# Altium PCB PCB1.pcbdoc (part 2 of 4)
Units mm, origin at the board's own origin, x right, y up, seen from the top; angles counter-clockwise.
Board outline 94.87 x 122.3 mm, 4 copper layers (Top Layer, Inner1, Inner2, Bottom Layer); 129 components, 127 nets, 714 pads, 326 vias.
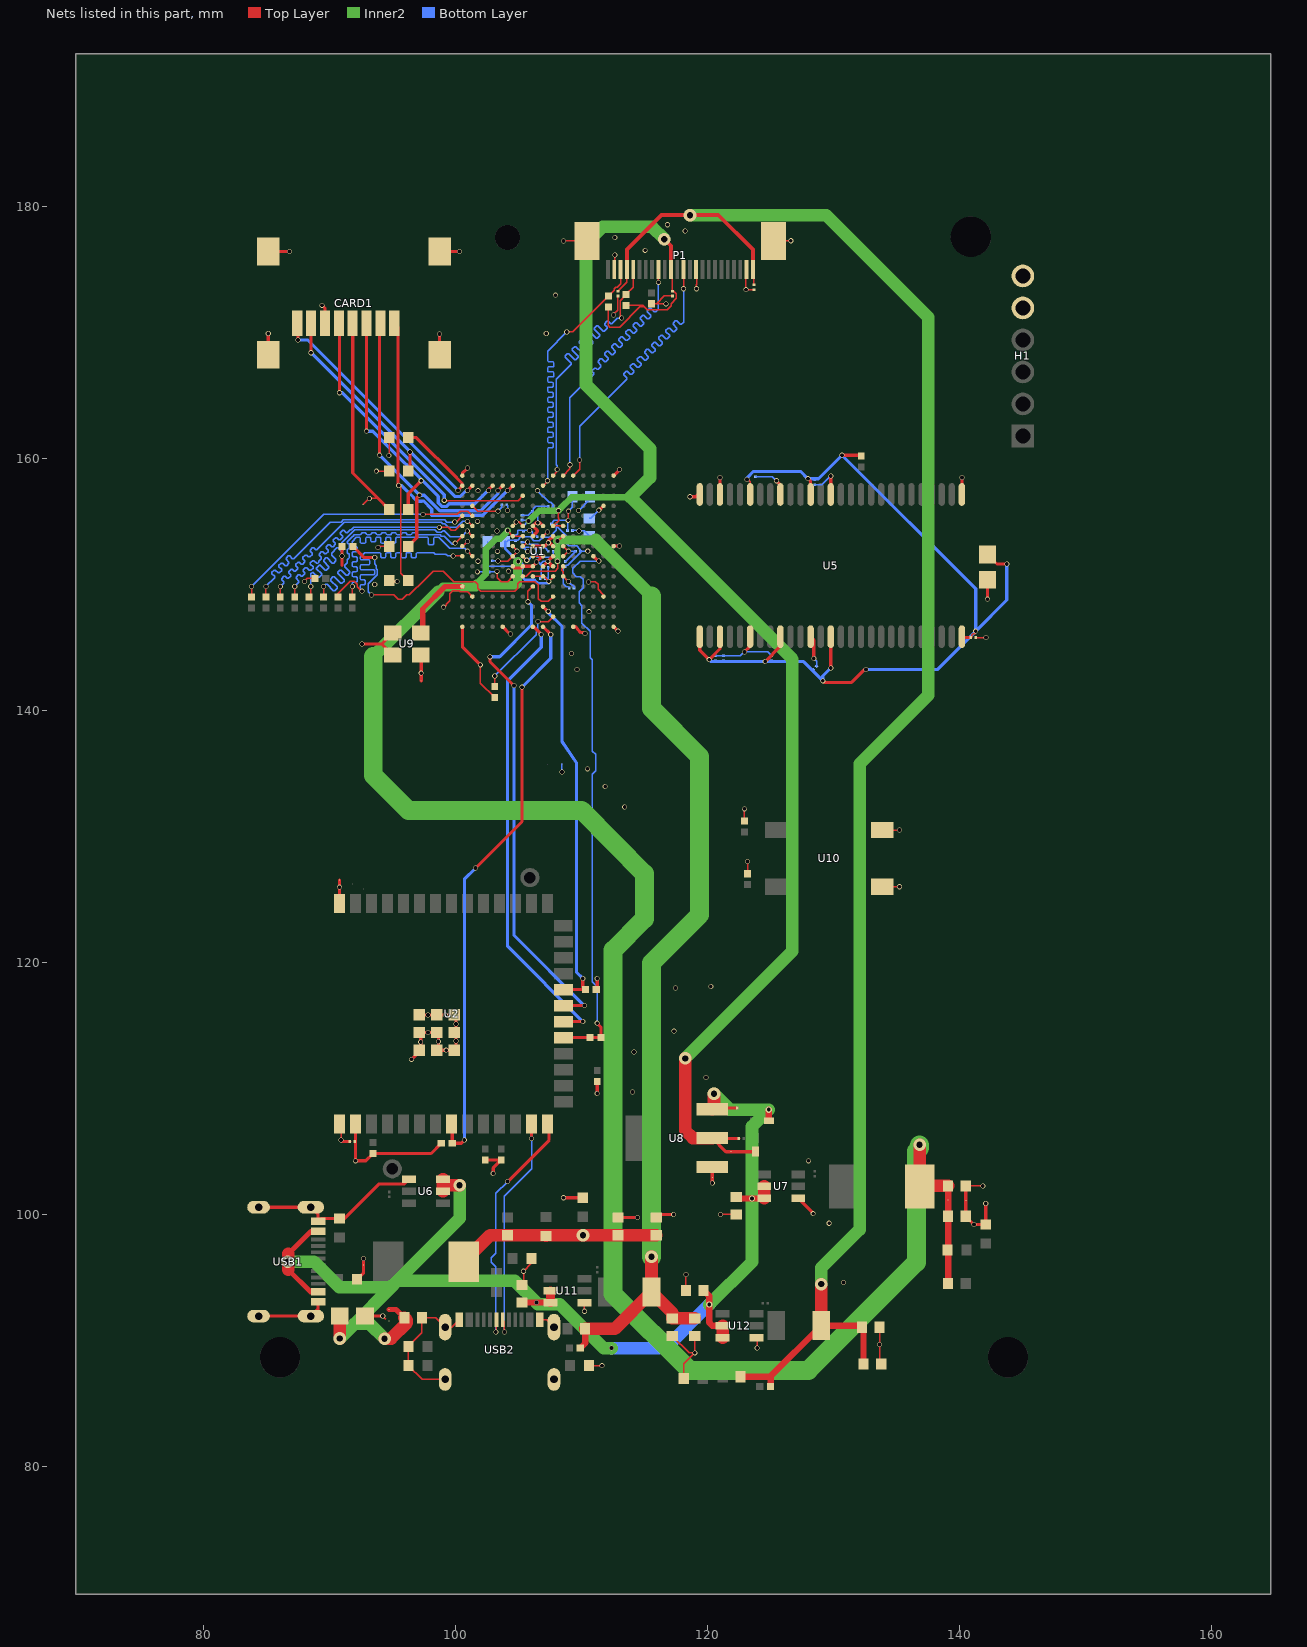
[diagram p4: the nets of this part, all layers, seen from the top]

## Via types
v1: diameter 0.4, hole 0.3, Top Layer to Bottom Layer, 311 vias
v2: diameter 1, hole 0.5, Top Layer to Bottom Layer, 12 vias
v3: diameter 0.5, hole 0.3, Top Layer to Bottom Layer, 3 vias

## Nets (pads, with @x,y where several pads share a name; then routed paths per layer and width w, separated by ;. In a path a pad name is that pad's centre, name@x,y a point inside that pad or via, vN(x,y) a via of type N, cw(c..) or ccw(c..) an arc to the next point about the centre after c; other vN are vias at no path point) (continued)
$2N5509: R24.2 U1.N10 | length 23.9
  Top Layer w0.1: v1(93.345,149.183) 95.104,149.183 95.464,148.823 95.798,148.823 96.158,149.183 96.351,149.183 97.595,150.427 97.595,150.432 98.231,151.068 99.024,151.068 99.856,150.236 101.567,150.236 101.771,150.032 101.771,149.696 101.995,149.472 103.911,149.472 103.918,149.479 104.388,149.479 104.395,149.472 104.711,149.472 104.935,149.696 104.935,150.054 105.117,150.236 106.311,150.236 106.571,149.976 106.571,148.896 106.795,148.672 107.371,148.672 U1.N10@107.753,149.054
  Top Layer w0.254: R24.2@91.873,153.035 92.762,152.146 v1(93.599,152.146)
  Bottom Layer w0.1: v1(93.345,149.183) 93.091,149.437 93.091,150.062 93.799,150.77 93.799,151.194 93.726,151.267 93.726,151.511 93.599,151.638 v1(93.599,152.146)
$2N5511: R25.2 U1.R10 | length 7.9
  Top Layer w0.1: R25.2@103.124,141.911 v1(103.124,142.748) ; v1(106.553,147.066) 107.365,147.066 U1.R10@107.753,147.454
  Bottom Layer w0.1: v1(103.124,142.748) 106.405,146.029 106.405,146.217 106.553,146.365 v1(106.553,147.066)
+1V1: C25.2 C27.2 C28.2 C41.1 C42.1 C43.1 C44.1 C49.1 C53.1 C54.1 C61.1 L2.2 pad.55@139.106,101.161 R15.2 U1.G6 U1.G7 U1.L8 U1.L9 U1.L10 | length 159.8
  Top Layer w0.1: v1@104.14,154.305 104.14,154.267 U1.G6@104.553,153.854 U1.G7@105.353,153.854 ; U1.L8@106.153,150.654 U1.L9@106.953,150.654 107.019,150.654 v1(107.412,150.262) 107.753,150.603 U1.L10@107.753,150.654
  Top Layer w0.5: C25.2@139.106,94.527 C28.2@139.106,99.861 pad.55@139.106,101.161 C27.2@139.106,102.274
  Top Layer w1: v2(136.842,105.537) L2.2@136.842,102.229 136.887,102.274 C27.2@139.106,102.274
  Inner2 w0.5: 101.639,149.81 101.651,149.821 101.651,150.075 102.404,150.829 102.404,152.808 103.247,153.651 103.553,153.651 104.148,154.246 v1(104.148,154.297)
  Inner2 w0.7: 98.629,149.429 99.01,149.81 101.639,149.81 ; 101.651,150.075 101.778,149.948 104.83,149.948 104.918,150.036 104.918,151.799 v1@104.962,151.844
  Inner2 w1: 93.482,144.282 98.629,149.429
  Inner2 w1.5: 93.482,144.282 93.482,134.864 96.266,132.08 110.016,132.08 112.608,129.488 112.608,129.454 114.998,127.064 114.998,123.464 112.522,120.988 112.522,93.695 118.587,87.63 128.016,87.63 136.588,96.202 136.588,105.029 136.842,105.283 v2(136.842,105.537)
  Bottom Layer w0.1: C61.1@104.078,153.416 104.182,153.52 104.93,153.52 105.203,153.792 105.923,153.792 106.23,153.485 106.674,153.485 106.963,153.776 107.482,153.776 108.018,154.313 108.018,154.559 ; C53.1@107.129,150.495 107.315,150.495 107.383,150.427 C49.1@107.383,151.384 ; C43.1@108.018,154.813 108.018,154.559 ; C44.1@109.034,153.543 109.034,153.654 108.129,154.559 108.018,154.559
  Bottom Layer w0.2: C61.1@103.951,153.416 103.951,152.883 v1(104.99,151.844) 105.118,151.844 105.212,151.75 105.212,151.746 105.318,151.64 105.318,151.224 C54.1@105.224,151.13 105.224,150.681 105.537,150.368 106.295,150.368 106.549,150.114 107.398,150.114 v1@107.412,150.127
+1V8: C29.1 C32.2 C35.1 C62.1 C63.1 P1.11 pad.55@121.87,104.992 R38.2 R39.2 U1.F10 U1.F11 U8.2 | length 124.4
  Top Layer w0.1: v1(108.185,155.869) 108.185,155.627 108.171,155.612 108.171,155.296 108.185,155.282 108.185,155.086 U1.F10@107.753,154.654 U1.F11@108.553,154.654 ; R38.2@112.141,172.033 112.141,171.57 112.137,171.566 112.137,170.565 112.268,170.434 113.05,170.434 114.649,172.033 114.985,172.033 ; R39.2@113.538,172.16 114.858,172.16 114.985,172.033 ; P1.11@117.11,175.02 117.209,174.922 117.209,173.823 117.221,173.811 C35.1@117.221,173.296 ; 117.332,173.296 117.533,173.095 117.533,172.717 117.115,172.299 117.115,172.121 116.797,171.802 115.216,171.802 114.985,172.033
  Top Layer w0.254: C29.1@122.487,106.045 120.419,106.045 121.472,104.992 pad.55@121.87,104.992 C32.2@123.825,104.992
  Top Layer w0.3: v2(116.586,177.419) 117.11,176.895 P1.11@117.11,175.02
  Top Layer w1: v2(118.237,112.395) 118.237,106.68 118.843,106.074 U8.2@120.39,106.074
  Inner2 w0.5: v1(105.801,155.054) 105.838,155.054 106.654,155.869 v1(108.185,155.869) 108.364,156.048 108.364,156.078 109.226,156.94 113.887,156.94
  Inner2 w1: v2(116.586,177.419) 115.607,178.398 111.686,178.398 110.363,177.075 110.363,165.862 115.443,160.782 115.443,158.496 113.887,156.94 126.746,144.082 126.746,120.904 v2(118.237,112.395)
  Bottom Layer w0.1: C63.1@105.283,155.126 105.729,155.126 v1(105.801,155.054) 105.41,154.663 C62.1@105.41,154.627
+2V5: C65.2 C67.2 C68.2 L3.2 R41.2 U1.G11 U1.L7 | length 86.3
  Top Layer w0.1: U1.L7@105.353,150.654 105.613,150.654 106.031,151.072 107.911,151.072 108.135,151.296 108.135,151.612 108.105,151.642 v1(108.105,151.854) ; v1(108.105,153.454) 108.505,153.854 U1.G11@108.553,153.854
  Top Layer w0.5: R41.2@109.907,89.408 110.301,89.802 C65.2@110.301,90.932
  Top Layer w1: C65.2@110.301,90.932 112.646,90.932 L3.2@115.567,93.853 ; v2(115.567,96.647) L3.2@115.567,93.853 ; C67.2@118.999,91.759 C68.2@117.221,91.759 117.221,92.199 L3.2@115.567,93.853
  Inner2 w0.5: v1(108.105,151.854) v1(108.105,153.454)
  Inner2 w0.7: v1(108.105,153.454) 108.194,153.543 111.125,153.543
  Inner2 w1: 111.125,153.543 115.567,149.101
  Inner2 w1.5: v2(115.567,96.647) 115.567,119.984 119.38,123.797 119.38,136.354 115.567,140.167 115.567,149.101
+2V8: C34.1 C70.2 C72.2 C73.2 C74.1 L4.2 P1.4 P1.24 R47.2 | length 139.5
  Top Layer w0.1: C34.1@112.903,173.296 113.611,174.004 P1.4@113.611,175.02 ; P1.24@123.612,175.017 123.698,174.931 C74.1@123.698,173.804
  Top Layer w0.3: P1.4@113.611,175.02 113.611,176.595 116.361,179.345 120.859,179.345 123.612,176.592 P1.24@123.612,175.017
  Top Layer w0.5: C70.2@122.62,87.122 124.965,87.122 ; R47.2@125.02,86.36 125.02,87.067 124.965,87.122 ; C73.2@132.269,91.059 132.142,91.186 L4.2@129.029,91.186 124.965,87.122 ; C72.2@132.396,88.138 C73.2@132.396,90.932
  Top Layer w1: L4.2@129.032,91.189 v2(129.032,94.488)
  Inner2 w1: v2(118.618,179.324) 129.413,179.324 137.541,171.196 137.541,141.224 132.08,135.763 132.08,98.806 129.032,95.758 v2(129.032,94.488)
+3V3: C8.1 C10.1 C11.1 C12.1 C13.1 C14.1 C15.2 C16.2 C17.2 C19.2 C22.2 C23.2 C37.1 C39.1 C40.1 C45.1 C46.1 C47.1 C48.1 C50.1 C51.1 C52.1 C55.1 C56.1 C57.1 C58.1 C59.1 CARD1.4 H1.5 L1.2 pad.55@92.679,156.358 R1.2 R3.1 R4.1 R5.2 R7.2 R11.2 R16.2 R17.2 R18.2 R19.2 R20.2 R21.2 R22.2 R23.1 U1.F6 U1.F7 U1.G9 U1.H6 U1.H7 U1.H11 U1.J6 U1.J7 U1.J11 U1.K11 U1.L6 U1.L11 U2.2 U5.1 U5.3 U5.9 U5.14 U5.27 U5.43 U5.49 U9.1 U9.4 | length 155.9
  Top Layer w0.1: v1(88.013,150.252) 88.256,150.495 R23.1@88.848,150.495 ; pad.55@92.679,156.358 v1(93.166,156.845) 93.858,156.845 93.86,156.847 ; v1(93.726,159.004) R18.2@94.751,159.004 ; v1(93.853,152.95) 93.938,153.035 R17.2@94.751,153.035 ; v1@94.751,160.274 R19.2@94.751,161.671 ; v1(103.305,151.054) 103.335,151.024 103.335,150.532 103.626,150.241 104.14,150.241 U1.L6@104.553,150.654 ; v1@103.378,151.892 103.575,151.892 103.595,151.872 104.171,151.872 U1.J6@104.553,152.254 104.881,152.582 v1(104.881,152.653) 104.881,152.726 U1.H6@104.553,153.054 ; U1.F6@104.553,154.654 104.821,154.922 v1(104.821,154.972) 105.035,154.972 U1.F7@105.353,154.654 ; U1.J7@105.353,152.254 105.664,151.943 v1@105.664,151.892 ; U1.H7@105.353,153.054 105.401,153.054 v1(105.737,153.39) ; U1.G9@106.953,153.854 107.277,154.178 v1(107.315,154.178) ; U1.K11@108.553,151.454 108.553,151.327 108.458,151.232 108.458,151.13 108.553,151.035 U1.L11@108.553,150.654 v1(108.966,150.241) ; U1.J11@108.553,152.254 108.953,152.654 v1(108.966,152.654) 108.566,153.054 U1.H11@108.553,153.054 ; v1(123.15,158.342) 123.217,158.342 123.394,158.165 U5.49@123.394,157.153 ; C14.1@140.902,145.796 140.985,145.879 140.985,145.99 141.103,146.108 141.214,146.108 141.292,146.186 v1(141.292,146.304)
  Top Layer w0.254: CARD1.4@91.848,170.739 91.848,158.859 93.86,156.847 R20.2@94.751,155.956 ; U2.2@92.197,107.201 92.075,107.079 v1(92.075,104.267) 92.889,104.267 R7.2@93.472,104.85 98.067,104.85 R5.2@98.881,105.664 ; v1(92.583,145.288) 94.164,145.288 ; R16.2@94.747,150.317 94.822,150.241 v1(95.377,150.241) ; U9.1@95.039,144.413 94.164,145.288 ; U9.4@95.039,146.163 94.164,145.288 ; R21.2@102.362,104.342 R22.2@103.632,104.342 102.997,103.707 v1(102.997,103.251) ; R3.1@111.177,117.856 111.252,117.931 v1(111.252,118.745) ; v1(111.252,109.601) R4.1@111.252,110.565 ; U5.1@119.394,145.996 119.394,144.787 v1(120.142,144.039) 120.994,144.891 U5.3@120.994,145.869 ; v1(124.587,143.891) 125.794,145.098 U5.9@125.794,145.869 ; v1(127.976,158.409) 128.194,158.191 U5.43@128.194,157.153 ; v1(129.159,142.367) 129.286,142.24 131.445,142.24 132.461,143.256 v1(132.588,143.256) ; v1(129.794,143.383) U5.14@129.794,145.869 ; v1(130.683,160.274) 132.132,160.274 R1.2@132.207,160.199 ; U5.27@140.194,145.869 140.267,145.796 C14.1@140.902,145.796 ; C8.1@142.24,152.384 142.986,151.638 v1(143.764,151.638)
  Top Layer w1: L1.2@100.663,96.266 102.757,98.36 C19.2@104.14,98.36 107.135,98.36 R11.2@107.188,98.307 107.241,98.36 v2(110.123,98.36) C23.2@112.903,98.36 C22.2@115.951,98.36
  Bottom Layer w0.1: C51.1@102.684,151.003 103.254,151.003 v1(103.305,151.054) ; C56.1@102.938,151.892 103.362,151.892 v1(103.37,151.884) ; C37.1@104.081,156.337 104.14,156.278 v1(104.14,155.889) ; C45.1@105.283,153.357 105.704,153.357 v1(105.737,153.39) 105.907,153.22 106.547,153.22 106.665,153.102 106.665,152.991 C46.1@106.748,152.908 107.12,152.908 C47.1@107.374,152.654 ; v1(105.664,151.933) 105.764,151.933 C57.1@106.104,152.273 ; C50.1@106.494,155.829 107.494,155.829 107.681,156.016 107.681,156.127 C39.1@107.764,156.21 107.764,156.321 107.563,156.522 107.437,156.522 v1(106.505,157.454) ; C52.1@108.712,151.833 C55.1@109.533,152.654 v1(108.966,152.654) ; v1(108.966,150.241) 109.162,150.045 109.214,150.045 109.415,149.844 C48.1@109.415,149.733 ; C40.1@109.288,154.305 109.75,154.305 v1(109.799,154.255) 110.221,154.255 C59.1@110.617,153.859 ; v1(109.777,155.877) 110.682,156.782 C58.1@110.682,156.972
  Bottom Layer w0.254: v1(120.142,144.039) 120.29,143.891 v1(124.587,143.891) 127.635,143.891 v1(129.159,142.367) 129.159,142.748 v1(129.794,143.383) ; v1(123.15,158.342) 123.15,158.49 123.638,158.977 127.408,158.977 v1(127.976,158.409) 128.818,158.409 v1(130.683,160.274) 141.292,149.665 v1(141.292,146.304) ; v1(132.588,143.256) 138.244,143.256 v1(141.292,146.304) ; v1(143.764,151.638) 143.764,148.776 v1(141.292,146.304)
  other v1: 93.599,150.001 94.717,160.241
+5V: C20.2 C26.2 C30.1 C31.2 C33.2 C66.2 C71.2 pad.55@94.723,92.475 U6.2 U6.3 U7.2 U7.3 U8.3 U11.2 U11.3 U12.2 U12.3 USB1.A4B9 USB1.B4A9 | length 109.8
  Top Layer w0.254: U8.3@120.39,108.374 U8.3@120.693,108.374 ; U8.3@120.777,108.458 C30.1@122.36,108.458
  Top Layer w0.4: 86.741,95.621 88.496,93.866 USB1.B4A9@89.103,93.866 ; 86.741,96.876 88.531,98.666 USB1.A4B9@89.103,98.666 ; pad.55@94.723,92.475 95.293,92.475 C20.2@95.947,91.821
  Top Layer w0.5: C66.2@105.283,93.026 v1(106.426,93.026) 107.518,93.026 U11.3@107.542,93.002 ; C71.2@119.699,93.98 120.142,93.537 v3(120.142,92.857) 120.142,91.44 120.396,91.186 U12.2@121.205,91.186 ; C26.2@122.301,101.411 122.427,101.285 v3(123.538,101.285) U7.3@124.507,101.285 ; C31.2@124.878,107.442 v3(124.878,108.331)
  Top Layer w0.7: U11.3@107.542,93.002 U11.2@107.542,93.952
  Top Layer w1: 86.741,95.621 86.741,96.876 ; v2(90.821,90.17) C33.2@90.821,91.948 ; v2(94.38,90.151) 94.888,90.151 96.137,91.401 96.137,91.63 C20.2@95.947,91.821 ; U6.2@99.013,101.856 99.013,102.335 ; U6.3@99.013,102.804 99.013,102.335 ; v2(100.33,102.335) 99.013,102.335 ; U8.3@120.39,108.374 120.523,108.507 v2(120.523,109.601) ; U12.3@121.205,90.236 U12.2@121.205,91.184 ; U7.3@124.507,101.285 U7.2@124.507,102.233
  Inner2 w1: v2(86.689,96.266) 88.773,96.266 90.805,94.234 94.869,94.234 ; v2(90.821,90.17) 91.979,91.328 ; v2(94.38,90.151) 93.203,91.328 91.979,91.328 ; v2(100.33,102.335) 100.33,99.695 95.377,94.742 ; v1(112.395,89.408) 111.76,89.408 108.269,92.899 106.553,92.899 v1(106.426,93.026) 104.71,94.742 95.377,94.742 ; v3(120.142,92.857) 123.538,96.253 v3(123.538,101.285) 123.538,106.991 v3(124.878,108.331) 121.793,108.331 v2(120.523,109.601) ; 91.979,91.328 94.869,94.218 94.869,94.234 ; 94.869,94.234 95.377,94.742
  Bottom Layer w1: v1(112.395,89.408) 116.693,89.408 v3(120.142,92.857)
CCLK: R6.1 R6.2 U1.J14 U2.19 | length 44.6
  Top Layer w0.254: U2.19@108.717,114.046 R6.1@110.692,114.046 R6.2@111.558,114.046 111.558,114.883 v1(111.252,115.189) ; U1.J14@110.953,152.254 111.336,151.871 v1(111.379,151.871)
  Bottom Layer w0.1: v1(111.252,115.189) 111.252,118.068 110.85,118.47 110.85,134.942 111.125,135.217 111.125,136.525 110.871,136.779 110.85,136.779 110.85,144.039 110.698,144.191 110.698,146.293 110.04,146.951 110.04,148.316 109.811,148.545 109.811,149.435 110.13,149.754 110.13,150.408 109.895,150.643 109.609,150.643 109.324,150.927 109.324,151.295 109.9,151.871 v1(111.379,151.871)
CRYSTAL: U1.M1 U9.3 | length 5.9
  Top Layer w0.4: U9.3@97.239,146.163 97.409,146.333 97.409,148.082 99.181,149.854 U1.M1@100.553,149.854
D0: R26.1 U1.E2 | length 21
  Top Layer w0.1: R26.1@83.82,149.023 v1(83.82,149.86) ; v1@97.409,155.575 100.134,155.575 100.395,155.836 100.971,155.836 U1.E2@101.353,155.454
  Bottom Layer w0.1: v1(83.82,149.86) 89.535,155.575 v1(97.419,155.575)
D1: R27.1 U1.E1 | length 21.1
  Top Layer w0.1: R27.1@84.963,149.023 v1(84.963,149.86) ; v1(99.949,154.969) 100.068,154.969 U1.E1@100.553,155.454
  Bottom Layer w0.1: v1(84.963,149.86) 85.648,150.545 85.648,150.645 85.431,150.863 85.431,150.963 85.613,151.145 85.713,151.145 85.931,150.928 86.031,150.928 86.214,151.111 86.214,151.211 85.996,151.428 85.996,151.528 86.179,151.711 86.279,151.711 86.497,151.494 86.597,151.494 86.779,151.676 86.779,151.776 86.562,151.994 86.562,152.094 86.745,152.277 86.845,152.277 87.062,152.059 87.162,152.059 90.072,154.969 90.932,154.969 91.11,155.147 99.142,155.147 99.32,154.969 v1(99.949,154.969)
D2: R28.1 U1.F2 | length 21.5
  Top Layer w0.1: R28.1@86.106,149.023 v1(86.106,149.86) ; v1(100.962,155.024) 100.983,155.024 U1.F2@101.353,154.654
  Bottom Layer w0.1: v1(86.106,149.86) 86.36,150.114 86.36,150.214 86.206,150.368 86.206,150.468 86.389,150.651 86.489,150.651 86.643,150.497 86.743,150.497 86.926,150.68 86.926,150.78 86.772,150.934 86.772,151.034 86.955,151.217 87.055,151.217 87.209,151.063 87.309,151.063 87.491,151.245 87.491,151.345 87.337,151.499 87.337,151.599 87.52,151.782 87.62,151.782 87.774,151.628 87.874,151.628 88.057,151.811 88.057,151.911 87.903,152.065 87.903,152.165 88.086,152.348 88.186,152.348 88.34,152.194 88.44,152.194 88.623,152.377 88.623,152.477 88.469,152.631 88.469,152.731 88.652,152.914 88.752,152.914 88.906,152.76 89.006,152.76 91.193,154.947 98.89,154.947 99,154.838 99.168,154.838 99.439,154.567 100.116,154.567 100.572,155.024 v1(100.962,155.024)
D3: R29.1 U1.F1 | length 20.7
  Top Layer w0.1: R29.1@87.249,149.023 v1(87.249,149.86) ; v1(98.724,154.545) 99.423,154.545 99.655,154.313 99.989,154.313 100.347,154.671 100.536,154.671 U1.F1@100.553,154.654
  Bottom Layer w0.1: v1(87.249,149.86) 87.568,150.179 87.568,150.279 87.351,150.497 87.351,150.597 87.534,150.78 87.634,150.78 87.753,150.66 87.853,150.66 88.036,150.843 88.036,150.943 87.916,151.062 87.916,151.162 88.099,151.345 88.199,151.345 88.417,151.128 88.517,151.128 88.7,151.311 88.7,151.411 88.482,151.628 88.482,151.728 88.665,151.911 88.765,151.911 88.983,151.694 89.083,151.694 89.135,151.746 89.135,151.842 89.347,152.055 89.347,152.155 89.178,152.324 89.178,152.424 89.361,152.607 89.461,152.607 89.63,152.437 89.73,152.437 89.913,152.62 89.913,152.72 89.744,152.89 89.744,152.99 89.926,153.172 90.026,153.172 90.196,153.003 90.296,153.003 90.479,153.186 90.479,153.286 90.309,153.455 90.309,153.555 90.492,153.738 90.592,153.738 90.761,153.569 90.861,153.569 91.044,153.752 91.044,153.852 90.875,154.021 90.875,154.121 91.058,154.304 91.158,154.304 91.327,154.134 91.427,154.134 91.636,154.343 91.732,154.343 91.934,154.545 v1(98.724,154.545)
D4: R30.1 U1.G2 | length 21.3
  Top Layer w0.1: R30.1@88.392,149.023 88.519,149.15 v1(88.519,149.86) ; v1(100.947,154.257) 100.95,154.257 U1.G2@101.353,153.854
  Bottom Layer w0.1: v1(88.519,149.86) 88.519,150.847 88.665,150.993 88.683,150.993 89.095,150.581 89.195,150.581 89.378,150.764 89.378,150.864 88.966,151.276 88.966,151.294 89.231,151.559 89.249,151.559 89.661,151.147 89.761,151.147 89.944,151.33 89.944,151.43 89.532,151.842 89.532,151.942 89.715,152.125 89.815,152.125 90.227,151.713 90.327,151.713 90.509,151.896 90.509,151.996 90.17,152.335 90.17,152.498 90.596,152.924 90.696,152.924 90.914,152.706 91.014,152.706 91.197,152.888 91.197,152.988 90.979,153.207 90.979,153.307 92.017,154.345 98.355,154.345 98.557,154.143 98.89,154.143 99.017,154.27 99.126,154.27 99.578,153.818 100.507,153.818 v1(100.947,154.257)
D5: R31.1 U1.G1 | length 21
  Top Layer w0.1: R31.1@89.535,149.023 v1(89.535,149.86) ; v1(99.983,153.289) 99.988,153.289 U1.G1@100.553,153.854
  Bottom Layer w0.1: v1(89.535,149.86) 89.714,150.039 89.814,150.039 90.323,149.53 90.423,149.53 90.606,149.713 90.606,149.813 90.097,150.322 90.097,150.422 90.279,150.604 90.379,150.604 90.889,150.095 90.989,150.095 91.171,150.278 91.171,150.378 90.662,150.887 90.662,150.987 90.826,151.151 90.926,151.151 91.338,150.739 91.438,150.739 91.621,150.921 91.621,151.021 91.209,151.434 91.209,151.534 91.409,151.734 91.409,151.992 91.48,152.062 91.521,152.062 91.592,152.133 91.592,152.392 91.521,152.462 91.48,152.462 91.409,152.533 91.409,152.792 91.48,152.862 91.521,152.862 91.592,152.933 91.592,153.192 91.521,153.262 91.48,153.262 91.409,153.333 91.409,153.407 91.855,153.853 91.877,153.853 91.967,153.943 92.452,153.943 92.523,154.014 92.523,154.045 92.594,154.116 92.852,154.116 92.923,154.045 92.923,154.014 92.994,153.943 93.252,153.943 93.323,154.014 93.323,154.045 93.394,154.116 93.652,154.116 93.723,154.045 93.723,154.014 93.794,153.943 94.052,153.943 94.123,154.014 94.123,154.045 94.194,154.116 94.452,154.116 94.523,154.045 94.523,154.014 94.594,153.943 94.852,153.943 94.923,154.014 94.923,154.045 94.994,154.116 95.252,154.116 95.323,154.045 95.323,154.014 95.394,153.943 95.652,153.943 95.723,154.014 95.723,154.045 95.794,154.116 96.052,154.116 96.123,154.045 96.123,154.014 96.194,153.943 96.452,153.943 96.523,154.014 96.523,154.045 96.594,154.116 96.852,154.116 96.923,154.045 96.923,154.014 96.994,153.943 98.778,153.943 98.868,153.853 99.097,153.853 99.751,153.199 99.893,153.199 v1(99.983,153.289)
D6: R32.1 U1.J1 | length 20.9
  Top Layer w0.1: R32.1@90.678,149.023 90.678,149.286 91.654,150.262 91.988,150.262 92.223,150.027 92.223,149.839 v1(92.583,149.479) ; v1(99.822,152.273) 100.534,152.273 U1.J1@100.553,152.254
  Bottom Layer w0.1: v1(92.583,149.479) 92.435,149.627 92.435,149.911 92.506,149.982 92.77,149.982 92.841,150.052 92.841,150.311 92.77,150.382 92.506,150.382 92.435,150.452 92.435,150.711 92.506,150.782 93.528,150.782 93.599,150.852 93.599,151.111 93.528,151.182 92.506,151.182 92.435,151.252 92.435,151.511 92.506,151.582 93.147,151.582 93.218,151.652 93.218,151.911 93.147,151.982 92.506,151.982 92.435,152.052 92.435,152.186 92.797,152.548 94.015,152.548 94.086,152.477 94.086,152.217 94.156,152.146 94.415,152.146 94.486,152.217 94.486,152.477 94.556,152.548 94.815,152.548 94.886,152.477 94.886,152.217 94.956,152.146 95.215,152.146 95.286,152.217 95.286,152.477 95.356,152.548 95.615,152.548 95.686,152.477 95.686,152.217 95.756,152.146 96.015,152.146 96.086,152.217 96.086,152.477 96.156,152.548 96.415,152.548 96.486,152.477 96.486,152.217 96.556,152.146 96.815,152.146 96.886,152.217 96.886,152.477 96.956,152.548 98.277,152.548 98.404,152.421 99.227,152.421 99.375,152.273 v1(99.822,152.273)
D7: R34.1 U1.J2 | length 21
  Top Layer w0.1: R34.1@91.821,149.023 v1(91.821,149.86) ; v1(100.965,152.654) 100.965,152.642 U1.J2@101.353,152.254
  Bottom Layer w0.1: v1(91.821,149.86) 91.821,150.134 91.892,150.205 92.135,150.205 92.206,150.276 92.206,150.534 92.135,150.605 91.892,150.605 91.821,150.676 91.821,150.934 91.892,151.005 92.135,151.005 92.206,151.076 92.206,151.334 92.135,151.405 91.892,151.405 91.821,151.476 91.821,151.734 91.892,151.805 92.135,151.805 92.206,151.876 92.206,152.134 92.135,152.205 91.892,152.205 91.821,152.276 91.821,152.534 91.892,152.605 92.135,152.605 92.206,152.676 92.206,152.934 92.135,153.005 91.892,153.005 91.821,153.076 91.821,153.416 92.148,153.743 92.397,153.743 92.467,153.672 92.467,153.334 92.538,153.263 92.797,153.263 92.867,153.334 92.867,153.672 92.938,153.743 93.197,153.743 93.267,153.672 93.267,153.475 93.338,153.405 93.597,153.405 93.667,153.475 93.667,153.672 93.738,153.743 93.997,153.743 94.067,153.672 94.067,153.334 94.138,153.263 94.397,153.263 94.467,153.334 94.467,153.672 94.538,153.743 94.797,153.743 94.867,153.672 94.867,153.334 94.938,153.263 95.197,153.263 95.267,153.334 95.267,153.672 95.338,153.743 97.792,153.743 97.862,153.672 97.862,153.233 97.933,153.162 98.192,153.162 98.262,153.233 98.262,153.672 98.333,153.743 98.696,153.743 99.552,152.887 100.732,152.887 v1(100.965,152.654)
DIN: U1.T8 U2.20 | length 36.6
  Top Layer w0.254: U1.T8@106.153,146.654 106.203,146.654 v1(106.807,146.05) ; U2.20@108.717,115.316 v1(110.109,115.316)
  Bottom Layer w0.254: v1(106.807,146.05) 106.807,145.034 104.14,142.367 104.14,121.285 v1(110.109,115.316)
DN: U2.13 USB2.A7 | length 18.5
  Top Layer w0.1: USB2.A7@103.755,91.643 103.886,91.512 v1(103.886,90.678)
  Top Layer w0.254: v1(106.045,106.045) 106.045,107.079 U2.13@106.167,107.201
  Bottom Layer w0.1: v1(103.886,90.678) 103.886,101.473 106.045,103.632 v1(106.045,106.045)
DONE: pad.55@109.093,136.525 R3.2 U1.P9 U2.22 | length 33.3
  Top Layer w0.254: U1.P9@106.953,148.254 107.323,147.884 v1(107.371,147.884) ; U2.22@108.717,117.856 R3.2@110.311,117.856 110.109,118.058 v1(110.109,118.745)
  Bottom Layer w0.254: v1(107.371,147.884) 107.371,147.772 108.458,146.685 108.458,137.541 109.601,135.89 109.601,119.253 v1(110.109,118.745)
DOUT: U1.M8 U2.21 | length 40
  Top Layer w0.1: v1(105.753,148.639) 105.753,149.454 U1.M8@106.153,149.854
  Top Layer w0.254: v1(102.743,144.272) 102.743,143.891 v1(104.648,141.986) ; U2.21@108.717,116.586 v1(110.236,116.586)
  Bottom Layer w0.254: v1(102.743,144.272) 103.505,144.272 106.037,146.804 106.037,148.355 v1(105.753,148.639) ; v1(104.648,141.986) 104.648,122.174 v1(110.236,116.586)
DP: U2.14 USB2.A6 | length 19.5
  Top Layer w0.1: v1@103.255,90.678 USB2.A6@103.255,91.643
  Top Layer w0.254: v1(104.14,102.616) 107.437,105.913 U2.14@107.437,107.201
  Bottom Layer w0.1: v1(103.207,90.678) 103.207,95.868 102.849,96.226 102.849,96.56 103.207,96.918 103.207,101.683 v1(104.14,102.616)
FSCL: P1.5 R39.1 U1.A10 | length 27
  Top Layer w0.1: U1.A10@107.753,158.654 108.077,158.978 v1(108.077,159.131) ; v1(113.2,171.153) 113.066,171.287 113.066,172.527 113.538,172.999 R39.1@113.538,173.026 114.11,173.598 P1.5@114.11,175.02
  Bottom Layer w0.1: v1(108.077,159.131) 108.077,159.417 107.996,159.497 107.996,166.288 109.185,167.477 109.185,167.577 108.713,168.049 108.713,168.149 108.896,168.332 108.996,168.332 109.468,167.86 109.568,167.86 109.751,168.043 109.751,168.143 109.279,168.615 109.279,168.715 109.462,168.898 109.562,168.898 110.034,168.426 110.134,168.426 110.317,168.609 110.317,168.709 109.845,169.181 109.845,169.281 110.028,169.464 110.128,169.464 110.6,168.991 110.7,168.991 110.883,169.174 110.883,169.274 110.46,169.696 110.46,169.796 110.643,169.979 110.743,169.979 111.165,169.557 111.265,169.557 111.448,169.74 111.448,169.84 111.026,170.262 111.026,170.362 111.209,170.545 111.309,170.545 111.731,170.123 111.831,170.123 112.037,170.328 112.037,170.428 111.847,170.618 111.847,170.718 112.03,170.901 112.13,170.901 112.32,170.711 112.42,170.711 112.861,171.153 v1(113.2,171.153)
FSDA: P1.3 R38.1 U1.B9 | length 27
  Top Layer w0.1: U1.B9@106.953,157.854 107.315,158.216 v1(107.315,158.242) ; v1(108.839,170.053) 109.295,170.053 R38.1@112.141,172.899 112.591,173.349 112.591,173.485 112.709,173.603 112.845,173.603 113.11,173.868 P1.3@113.11,175.02
  Bottom Layer w0.1: v1(107.315,158.242) 107.315,160.796 107.386,160.867 107.702,160.867 107.773,160.938 107.773,161.196 107.702,161.267 107.386,161.267 107.315,161.338 107.315,161.607 107.386,161.678 107.702,161.678 107.773,161.748 107.773,162.007 107.702,162.078 107.386,162.078 107.315,162.148 107.315,162.407 107.386,162.478 107.702,162.478 107.773,162.548 107.773,162.807 107.702,162.878 107.386,162.878 107.315,162.948 107.315,163.207 107.386,163.278 107.702,163.278 107.773,163.348 107.773,163.607 107.702,163.678 107.386,163.678 107.315,163.748 107.315,164.007 107.386,164.078 107.702,164.078 107.773,164.148 107.773,164.407 107.702,164.478 107.386,164.478 107.315,164.548 107.315,164.807 107.386,164.878 107.702,164.878 107.773,164.948 107.773,165.207 107.702,165.278 107.386,165.278 107.315,165.348 107.315,165.607 107.386,165.678 107.702,165.678 107.773,165.748 107.773,166.007 107.702,166.078 107.386,166.078 107.315,166.148 107.315,166.407 107.386,166.478 107.752,166.478 107.823,166.548 107.823,166.807 107.752,166.878 107.386,166.878 107.315,166.948 107.315,167.207 107.386,167.278 107.752,167.278 107.823,167.348 107.823,167.607 107.752,167.678 107.386,167.678 107.315,167.748 107.315,168.529 v1(108.839,170.053)
GND: C8.2 C10.2 C11.2 C12.2 C13.2 C14.2 C15.1 C16.1 C17.1 C20.1 C22.1 C23.1 C26.1 C27.1 C28.1 C33.1 C34.2 C35.2 C37.2 C39.2 C40.2 C41.2 C42.2 C43.2 C44.2 C45.2 C46.2 C47.2 C48.2 C49.2 C50.2 C51.2 C52.2 C53.2 C54.2 C55.2 C56.2 C57.2 C58.2 C59.2 C61.2 C62.2 C63.2 C66.1 C67.1 C68.1 C71.1 C72.1 C73.1 C74.2 CARD1.6 CARD1.9 CARD1.10 CARD1.11 CARD1.12 H1.6 P1.2 P1.15 P1.23 P1.25 P1.26 pad.55@90.8,126.56 pad.55@92.71,96.012 pad.55@94.742,91.567 pad.55@97.282,142.367 pad.55@108.458,135.763 pad.55@120.39,102.962 pad.55@140.506,101.121 R9.1 R10.1 R12.1 R14.1 R24.1 R25.1 R35.2 R36.2 R37.2 R40.1 R42.2 R43.2 R45.1 R46.1 U1.A1 U1.A16 U1.D2 U1.D15 U1.F8 U1.F9 U1.G8 U1.G10 U1.H1 U1.H8 U1.H9 U1.H10 U1.H16 U1.J8 U1.J9 U1.J10 U1.K6 U1.K7 U1.K8 U1.K9 U1.K10 U1.N2 U1.N15 U1.T1 U1.T5 U1.T12 U1.T16 U2.1 U2.40 U2.41 U5.6 U5.12 U5.28 U5.41 U5.46 U5.52 U5.54 U6.4 U7.4 U8.1 U9.2 U10.2 U10.4 U11.4 U12.4 USB1.1 USB1.2 USB1.3 USB1.4 USB1.A1B12 USB1.B1A12 USB2.1 USB2.2 USB2.3 USB2.4 USB2.A1B12 USB2.B1A12 | length 193.3
  Top Layer w0.1: U2.1@90.8,107.201 90.927,107.074 v1(90.927,105.918) ; v1(94.234,91.948) 94.488,91.694 ; v1(99.06,148.209) 99.134,148.209 99.293,148.368 99.293,148.453 99.547,148.707 99.547,149.265 99.782,149.5 100.309,149.5 100.367,149.442 100.965,149.442 U1.N2@101.353,149.054 ; USB2.3@99.185,86.919 97.367,86.919 R42.2@96.275,88.011 R43.2@96.275,89.535 97.347,90.607 C20.1@97.347,91.821 98.432,91.821 USB2.1@99.185,91.068 99.73,91.068 USB2.A1B12@100.305,91.643 ; 100.711,153.162 100.953,153.404 v1(100.953,153.416) ; U1.D2@101.353,156.254 101.778,155.829 101.988,155.829 101.995,155.836 103.111,155.836 103.118,155.829 v1@103.378,155.829 ; v1(101.981,143.637) 101.981,142.188 R25.1@103.124,141.045 ; C66.1@105.283,94.426 105.41,94.553 v1(105.41,95.504) 106.036,96.13 R45.1@106.036,96.52 ; U1.J8@106.153,152.254 U1.J9@106.896,152.254 ; USB2.B1A12@106.705,91.643 107.25,91.643 USB2.2@107.825,91.068 ; v1(108.585,177.274) P1.26@110.455,177.274 ; v1(108.953,155.102) 108.966,155.115 v1(108.966,155.829) ; v1(110.236,92.329) 110.242,92.335 U11.4@110.242,93.002 ; v1(110.553,150.206) 110.692,150.206 110.722,150.236 111.111,150.236 111.335,150.012 111.335,149.623 111.753,149.205 U1.N15@111.753,149.054 ; R40.1@110.608,88.011 v1(111.633,88.011) ; v1(112.539,171.4) 112.539,171.467 112.866,171.794 112.866,172.61 112.903,172.647 C34.2@112.903,172.906 ; P1.2@112.611,175.02 112.649,175.059 v1(112.649,176.149) ; R35.2@115.57,172.287 115.967,172.287 ; v1(116.713,172.287) 115.967,172.287 ; C68.1@117.221,90.359 118.553,89.027 v1(118.999,89.027) ; C35.2@117.221,172.906 116.586,172.906 115.967,172.287 ; R46.1@118.119,86.995 118.119,88.147 v1(118.999,89.027) ; C71.1@118.299,93.98 v1(118.299,95.25) ; C67.1@118.999,90.359 v1(118.999,89.027) ; P1.15@119.107,175.019 119.143,174.982 119.143,173.82 119.126,173.802 v1@119.126,173.482 ; v1(121.031,100.011) C26.1@122.301,100.011 ; R36.2@122.936,131.243 v1(122.936,132.207) ; P1.23@123.112,175.017 123.063,174.968 v1(123.063,173.41) 123.067,173.414 C74.2@123.698,173.414 ; R37.2@123.19,127.052 v1(123.19,128.016) ; U12.4@123.905,90.236 123.952,90.189 v1(123.952,89.408) ; P1.25@125.257,177.281 126.608,177.281 v1(126.619,177.292) ; C73.1@133.669,91.059 v1(133.669,89.688) 133.669,88.265 C72.1@133.796,88.138 ; U10.4@133.867,126.02 v1(135.255,126.02) ; U10.2@133.867,130.52 v1(135.255,130.52) ; C27.1@140.506,102.274 v1(141.859,102.274) ; C14.2@141.292,145.796 v1(142.113,145.796)
  Top Layer w0.254: USB1.4@84.379,91.946 USB1.2@88.528,91.946 89.103,92.521 USB1.B1A12@89.103,93.066 ; USB1.3@84.379,100.586 USB1.1@88.528,100.586 89.103,100.011 USB1.A1B12@89.103,99.466 89.324,99.686 R9.1@90.805,99.686 91.186,99.686 93.923,102.423 95.637,102.423 95.647,102.433 95.942,102.433 U6.4@96.313,102.804 ; CARD1.10@85.148,168.239 v1(85.148,169.93) ; CARD1.9@85.148,176.439 v1(86.833,176.439) ; v1(89.421,172.166) 89.648,171.939 CARD1.6@89.648,170.739 ; pad.55@90.8,126.56 v1(90.8,125.988) 90.8,124.828 U2.40@90.927,124.701 ; v1(90.927,105.918) 91.054,105.791 C17.1@91.626,105.791 ; 91.007,151.511 v1(91.007,152.267) R24.1@91.007,153.035 ; R10.1@92.193,94.869 92.71,95.386 pad.55@92.71,96.012 v1(92.71,96.52) ; C33.1@92.821,91.948 v1(94.234,91.948) ; v1(96.521,112.325) 97.247,113.051 v1(97.247,113.704) 97.247,114.451 v1(97.823,114.451) 98.647,114.451 v1(98.647,113.729) 98.647,113.051 v1(99.267,113.051) 100.047,113.051 v1(100.047,113.773) v1(100.047,115.135) 100.047,115.851 v1(99.198,115.851) U2.41@98.52,115.851 v1(97.823,115.851) U2.41@97.247,115.851 ; U9.2@97.239,144.413 97.282,144.37 v1(97.282,142.972) pad.55@97.282,142.367 ; CARD1.11@98.748,168.239 v1(98.748,169.888) ; CARD1.12@98.748,176.439 v1(100.33,176.439) ; U1.T1@100.553,146.654 100.553,145.065 v1(101.981,143.637) ; U1.A1@100.553,158.654 100.553,158.846 v1(100.965,159.258) ; U1.T5@103.753,146.654 104.336,146.071 v1(104.373,146.071) ; U1.K6@104.553,151.454 104.694,151.313 105.212,151.313 U1.K7@105.353,151.454 U1.K8@106.153,151.454 106.44,151.741 v1(106.44,151.797) 106.896,152.254 U1.J9@106.953,152.254 ; U1.H8@106.153,153.054 U1.H9@106.953,153.054 107.104,153.054 v1(107.372,153.322) ; U1.G8@106.153,153.854 106.505,154.206 106.505,154.302 U1.F8@106.153,154.654 106.407,154.908 v1(106.544,154.908) 106.699,154.908 U1.F9@106.953,154.654 ; U1.K9@106.953,151.454 107.332,151.833 v1(107.332,151.846) ; U1.K10@107.597,151.482 107.597,151.58 v1(107.332,151.846) ; U1.J10@107.753,152.254 107.74,152.254 v1(107.332,151.846) ; U1.H10@107.753,153.054 107.485,153.322 v1(107.372,153.322) ; U1.G10@107.753,153.854 107.372,153.473 v1(107.372,153.322) ; v1(108.585,101.337) R12.1@110.109,101.337 ; U1.T12@109.353,146.654 109.54,146.654 109.694,146.5 109.694,146.464 109.963,146.195 110.223,146.195 v1(110.296,146.122) ; v1@111.379,155.956 111.455,155.956 U1.D15@111.753,156.254 ; U1.T16@112.553,146.654 v1(112.903,146.304) ; U1.H16@112.553,153.054 v1(113.03,153.056) ; U1.A16@112.553,158.654 v1(113.03,159.131) ; C23.1@112.903,99.76 v1(114.457,99.76) ; C22.1@115.951,99.76 116.202,100.011 v1(117.322,100.011) ; v1(118.618,156.972) 119.086,156.972 U5.54@119.394,157.28 ; v1(120.39,102.499) pad.55@120.39,102.962 U8.1@120.39,103.774 ; U5.52@120.994,157.28 v1(120.994,158.496) ; v1(122.936,144.653) 123.394,145.111 U5.6@123.394,145.869 ; v1(125.476,158.242) 125.794,157.924 U5.46@125.794,157.153 ; U7.4@127.207,101.285 128.397,100.095 v1(128.397,100.076) ; U5.12@128.194,145.869 128.448,145.615 v1(128.448,144.145) ; U5.41@129.794,157.28 v1(129.794,158.623) ; U5.28@140.194,157.153 140.208,157.167 v1(140.208,158.496) ; C27.1@140.506,102.274 pad.55@140.506,101.121 C28.1@140.506,99.861 v1(141.15,99.217) R14.1@142.092,99.217 v1(142.092,100.877) ; v1(142.24,148.844) C8.2@142.24,150.384
  Bottom Layer w0.1: v1@101.727,151.003 C51.2@102.294,151.003 102.294,151.114 102.548,151.368 ; C61.2@102.551,153.416 102.551,151.895 C56.2@102.548,151.892 102.548,151.368 ; v1(103.377,155.83) 103.691,156.144 C37.2@103.691,156.337 ; C41.2@104.775,153.865 104.953,154.043 104.953,154.302 105.345,154.302 C62.2@105.41,154.237 105.475,154.302 v1(105.88,154.302) 105.98,154.302 106.103,154.179 106.103,154.119 106.339,153.883 106.399,153.883 C42.2@106.485,153.797 ; C54.2@104.834,151.13 104.508,151.456 102.636,151.456 102.548,151.368 ; C45.2@105.283,152.967 C45.2@105.392,152.967 ; C63.2@105.283,155.516 105.791,155.516 C50.2@106.104,155.829 ; v1(105.739,152.621) C45.2@105.392,152.967 ; v1(106.44,151.797) 106.579,151.797 106.822,151.555 ; v1(106.544,154.908) 106.544,155.389 106.416,155.517 106.305,155.517 106.187,155.635 106.187,155.746 C50.2@106.104,155.829 ; C53.2@106.739,150.495 106.822,150.578 106.822,151.284 106.922,151.384 C49.2@106.993,151.384 106.822,151.555 ; C39.2@107.374,156.21 106.374,156.21 106.187,156.023 106.187,155.912 C50.2@106.104,155.829 ; C43.2@107.628,154.813 107.711,154.896 107.711,155.007 107.829,155.125 108.207,155.125 108.23,155.102 v1(108.953,155.102) 108.898,155.047 C40.2@108.898,154.305 ; C47.2@107.764,152.654 107.764,152.278 107.664,152.178 ; v1(108.458,135.128) pad.55@108.458,135.763 ; C44.2@108.644,153.543 108.644,153.432 109.01,153.066 109.622,153.066 109.923,152.765 C55.2@109.923,152.654 ; v1(108.966,155.829) 109.282,156.145 C58.2@109.282,156.972 ; C48.2@109.025,149.733 108.919,149.839 108.799,149.839 108.564,150.074 108.564,151.295 C52.2@108.712,151.443 108.795,151.526 108.906,151.526 109.923,152.543 C55.2@109.923,152.654 ; v1@110.49,152.654 C55.2@109.923,152.654 ; C59.2@110.617,155.259 110.73,155.259 v1(111.379,155.909) ; C10.2@120.65,144.34 C11.2@121.285,144.34 122.623,144.34 v1(122.936,144.653) 124.782,144.653 C12.2@125.095,144.34 ; C16.1@123.825,158.555 125.163,158.555 v1(125.476,158.242) ; v1(128.448,144.145) 128.662,143.931 C13.2@128.662,143.521 ; C15.1@128.524,157.92 129.091,157.92 v1(129.794,158.623) ; C45.2@105.392,152.967 106.299,152.967 C46.2@106.358,152.908 106.411,152.855 106.411,152.356 C57.2@106.494,152.273 106.589,152.178 107.664,152.178 ; 106.822,151.555 106.822,151.696 106.972,151.846 v1(107.332,151.846) 107.664,152.178
  other v1: 130.81,94.615 129.667,99.314 128.016,104.267 114.046,109.728 119.888,110.871 114.173,112.903 117.348,114.554 117.475,117.983 120.269,118.11 113.434,132.357 111.887,133.985 110.49,135.382 109.657,143.256 109.22,144.526 110.597,147.85 101.742,151.018 104.216,151.065 101.802,151.853 103.34,152.641 110.505,152.654 103.304,154.253 101.755,155.024 101.802,157.453 107.209,169.926 107.95,172.974 119.143,173.482 115.062,176.53 112.649,177.546 118.237,178.054 116.84,178.562
HREF: P1.9 U1.A11 | length 27
  Top Layer w0.1: U1.A11@108.553,158.654 109.093,159.194 v1(109.093,159.512) ; v1(116.11,173.99) P1.9@116.11,175.02
  Bottom Layer w0.1: v1(109.093,159.512) 109.093,164.846 110.961,166.714 110.961,166.814 110.871,166.905 110.871,167.005 111.054,167.188 111.154,167.188 111.244,167.097 111.344,167.097 111.555,167.308 111.555,167.408 111.324,167.639 111.324,167.739 111.507,167.922 111.607,167.922 111.838,167.691 111.938,167.691 112.121,167.874 112.121,167.974 111.84,168.255 111.84,168.355 112.023,168.538 112.123,168.538 112.404,168.257 112.504,168.257 112.687,168.44 112.687,168.54 112.406,168.821 112.406,168.921 112.589,169.104 112.689,169.104 112.97,168.823 113.07,168.823 113.252,169.005 113.252,169.105 112.971,169.386 112.971,169.486 113.154,169.669 113.254,169.669 113.535,169.388 113.635,169.388 113.818,169.571 113.818,169.671 113.537,169.952 113.537,170.052 113.72,170.235 113.82,170.235 114.101,169.954 114.201,169.954 114.384,170.137 114.384,170.237 114.103,170.518 114.103,170.618 114.286,170.801 114.386,170.801 114.667,170.52 114.767,170.52 114.95,170.703 114.95,170.803 114.669,171.084 114.669,171.184 114.851,171.366 114.951,171.366 115.232,171.085 115.332,171.085 115.515,171.268 115.515,171.368 115.234,171.649 115.234,171.749 115.417,171.932 115.517,171.932 115.798,171.651 115.898,171.651 116.11,171.863 v1(116.11,173.99)
INITN: pad.55@100.711,126.619 R5.1 U1.T9 U2.8 | length 46.5
  Top Layer w0.254: U2.8@99.817,107.201 99.747,107.131 R5.1@99.747,105.664 100.457,105.664 v1(100.711,105.918) ; v1(101.6,127.508) 105.283,131.191 v1(105.283,141.859) ; U1.T9@106.953,146.654 107.557,146.05 v1(107.569,146.05)
  Bottom Layer w0.254: v1(100.711,105.918) pad.55@100.711,126.619 v1(101.6,127.508) ; v1(105.283,141.859) 107.569,144.145 v1(107.569,146.05)
M_CLK: CARD1.5 U1.C7 | length 24
  Top Layer w0.1: v1(99.115,156.69) 99.132,156.672 104.971,156.672 U1.C7@105.353,157.054
  Top Layer w0.254: CARD1.5@90.748,170.739 90.805,170.682 v1(90.805,165.227)
  Bottom Layer w0.254: v1(90.805,165.227) 91.017,165.227 99.115,157.129 v1(99.115,156.69)
M_CMD: CARD1.3 R20.1 U1.B4 | length 24.7
  Top Layer w0.254: v1(92.948,162.179) CARD1.3@92.948,170.739 ; R20.1@96.257,155.956 96.257,157.217 v1(97.282,158.242) ; v1(102.616,157.48) 102.616,157.517 U1.B4@102.953,157.854
  Bottom Layer w0.254: v1(92.948,162.179) 93.456,162.179 98.636,156.999 98.636,156.491 98.916,156.211 99.313,156.211 99.512,156.41 101.546,156.41 v1(102.616,157.48)
M_D0: CARD1.7 R18.1 U1.B2 | length 21.8
  Top Layer w0.254: v1(88.548,168.402) CARD1.7@88.548,170.739 ; R18.1@96.257,159.004 96.393,159.14 v1(96.393,160.528) ; v1(100.965,157.48) 100.979,157.48 U1.B2@101.353,157.854
  Bottom Layer w0.254: v1(88.548,168.402) 99.949,157.001 100.401,157.001 100.88,157.48 v1(100.965,157.48)
M_D1: CARD1.8 R19.1 U1.B1 | length 25.5
  Top Layer w0.254: CARD1.8@87.448,170.739 87.503,170.684 v1(87.503,169.418) ; R19.1@96.257,161.671 96.892,161.671 100.094,158.469 100.094,158.464 100.363,158.195 100.368,158.195 100.52,158.043 U1.B1@100.52,157.821 ; v1(100.203,157.48) 100.203,157.504 U1.B1@100.52,157.821 ; U1.B1@100.553,157.854 U1.B1@100.52,157.821
  Bottom Layer w0.254: v1(87.503,169.418) 88.265,169.418 v1(100.203,157.48)
M_D2: CARD1.1 R16.1 U1.B6 | length 32.2
  Top Layer w0.1: v1(95.504,157.861) 95.652,157.713 95.652,150.918 R16.1@96.253,150.317
  Top Layer w0.254: CARD1.1@95.148,170.739 95.433,170.454 95.433,157.932 v1(95.504,157.861) ; v1(104.14,157.48) 104.179,157.48 U1.B6@104.553,157.854
  Bottom Layer w0.254: v1(95.504,157.861) 95.758,157.861 96.676,156.943 96.676,156.901 96.957,156.62 97.353,156.62 97.367,156.634 97.492,156.634 98.129,155.997 98.129,155.503 102.163,155.503 v1(104.14,157.48)
M_D3: CARD1.2 R17.1 U1.B5 | length 27.5
  Top Layer w0.254: v1(93.98,160.274) 93.98,170.671 CARD1.2@94.048,170.739 ; R17.1@96.257,153.035 96.94,153.717 96.94,156.884 v1(97.155,157.099) ; v1(103.378,157.48) U1.B5@103.753,157.854
  Bottom Layer w0.254: v1(93.98,160.274) v1(97.155,157.099) 97.527,157.099 98.77,155.857 102.016,155.857 103.378,157.219 v1(103.378,157.48)
MCLK: P1.13 U1.A12 | length 27.1
  Top Layer w0.1: U1.A12@109.353,158.654 109.855,159.156 v1(109.855,159.893) ; v1(118.11,173.482) P1.13@118.11,175.02
  Bottom Layer w0.1: v1(109.855,159.893) 109.855,162.56 113.6,166.305 113.6,166.405 113.369,166.636 113.369,166.736 113.552,166.919 113.652,166.919 113.883,166.688 113.983,166.688 114.166,166.871 114.166,166.971 113.885,167.252 113.885,167.352 114.068,167.535 114.168,167.535 114.449,167.254 114.549,167.254 114.731,167.436 114.731,167.536 114.45,167.817 114.45,167.917 114.633,168.1 114.733,168.1 115.014,167.819 115.114,167.819 115.297,168.002 115.297,168.102 115.016,168.383 115.016,168.483 115.199,168.666 115.299,168.666 115.58,168.385 115.68,168.385 115.863,168.568 115.863,168.668 115.582,168.949 115.582,169.049 115.765,169.232 115.865,169.232 116.146,168.951 116.246,168.951 116.428,169.133 116.428,169.233 116.147,169.514 116.147,169.614 116.33,169.797 116.43,169.797 116.711,169.516 116.811,169.516 116.994,169.699 116.994,169.799 116.713,170.08 116.713,170.18 116.896,170.363 116.996,170.363 117.277,170.082 117.377,170.082 117.56,170.265 117.56,170.365 117.279,170.646 117.279,170.746 117.462,170.929 117.562,170.929 117.843,170.648 117.943,170.648 118.11,170.815 v1(118.11,173.482)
